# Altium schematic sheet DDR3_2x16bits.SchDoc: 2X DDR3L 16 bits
size A4; Date: 30-MAR-2016; Author: F.L; CompanyName: STMicroelectronics; Organization: MCD/TOOLS/LMS; Address1: 12, Rue Jules HOROWITZ; Address2: 38019 Grenoble; Address3: FRANCE; DocumentNumber: MB1263; Revision: C-04; SheetNumber: 8; SheetTotal: 11; Project: STM32MP157-EVAL; PageSetup: Record=PageOptions¦CenterHorizontal=True¦CenterVertical=True¦PrintScale=1.39¦XCorrection=1.00¦YCorrection=1.00¦PrintKind=1¦BorderSize=5000000¦LeftOffset=0¦BottomOffset=0¦Orientation=2¦PaperLength=1000¦PaperWidth=1000¦Scale=100¦PaperSource=15¦PrintQuality=600¦MediaType=1¦DitherType=10¦PrintScaleMode=1¦PaperKind=A3¦PaperIndex=8
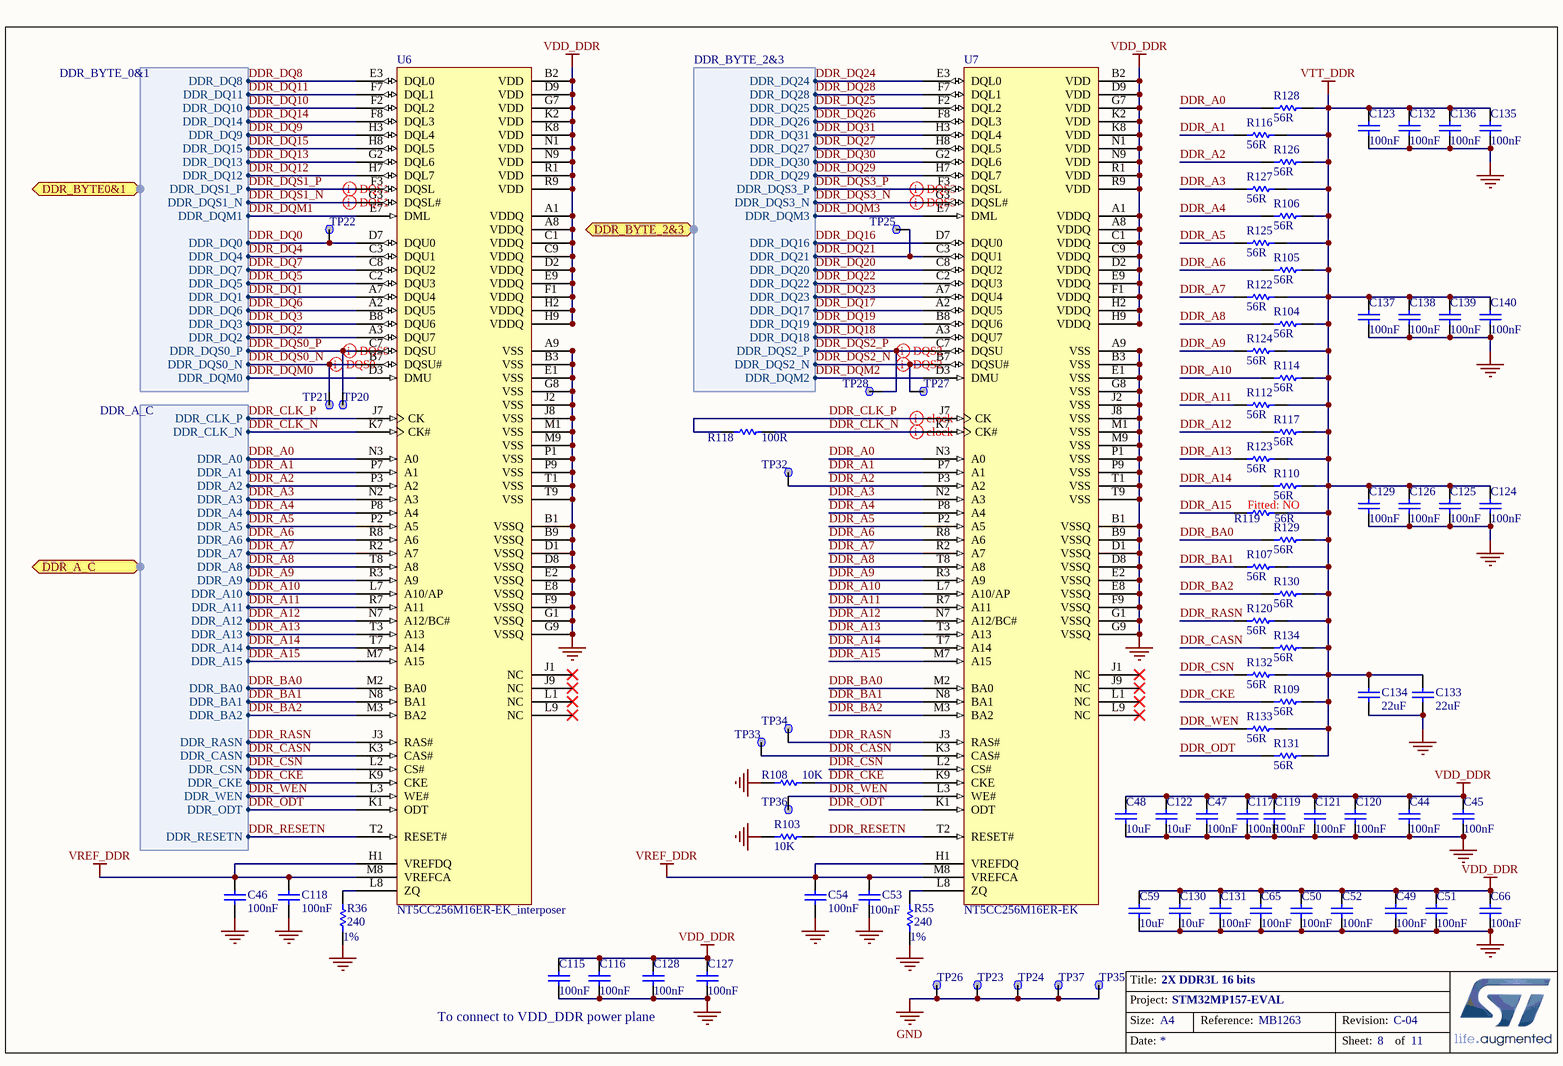
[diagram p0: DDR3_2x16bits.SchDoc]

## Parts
C44  100nF  [C0402]
C45  100nF  [C0402]
C46  100nF  [C0402]
C47  100nF  [C0402]
C48  10uF  [C0603]
C49  100nF  [C0402]
C50  100nF  [C0402]
C51  100nF  [C0402]
C52  100nF  [C0402]
C53  100nF  [C0402]
C54  100nF  [C0402]
C59  10uF  [C0603]
C65  100nF  [C0402]
C66  100nF  [C0402]
C115  100nF  [C0402]
C116  100nF  [C0402]
C117  100nF  [C0402]
C118  100nF  [C0402]
C119  100nF  [C0402]
C120  100nF  [C0402]
C121  100nF  [C0402]
C122  10uF  [C0603]
C123  100nF  [C0402]
C124  100nF  [C0402]
C125  100nF  [C0402]
C126  100nF  [C0402]
C127  100nF  [C0402]
C128  100nF  [C0402]
C129  100nF  [C0402]
C130  10uF  [C0603]
C131  100nF  [C0402]
C132  100nF  [C0402]
C133  22uF  [C0603]
C134  22uF  [C0603]
C135  100nF  [C0402]
C136  100nF  [C0402]
C137  100nF  [C0402]
C138  100nF  [C0402]
C139  100nF  [C0402]
C140  100nF  [C0402]
R36  240  Precision: 1%  [R0402]
R55  240  Precision: 1%  [R0402]
R103  10K  [R0402]
R104  56R  [R0402]
R105  56R  [R0402]
R106  56R  [R0402]
R107  56R  [R0402]
R108  10K  [R0402]
R109  56R  [R0402]
R110  56R  [R0402]
R112  56R  [R0402]
R114  56R  [R0402]
R116  56R  [R0402]
R117  56R  [R0402]
R118  100R  [R0402]
R119  56R  Fitted: NO  [R0402]
R120  56R  [R0402]
R122  56R  [R0402]
R123  56R  [R0402]
R124  56R  [R0402]
R125  56R  [R0402]
R126  56R  [R0402]
R127  56R  [R0402]
R128  56R  [R0402]
R129  56R  [R0402]
R130  56R  [R0402]
R131  56R  [R0402]
R132  56R  [R0402]
R133  56R  [R0402]
R134  56R  [R0402]
TP20  TP 0.3  [TP_SMD_0-3MM]  (value not drawn)  (no BOM)
TP21  TP 0.3  [TP_SMD_0-3MM]  (value not drawn)  (no BOM)
TP22  TP 0.6  [TP_SMD_0-6MM]  (value not drawn)  (no BOM)
TP23  TP 0.6  [TP_SMD_0-6MM]  (value not drawn)  (no BOM)
TP24  TP 0.6  [TP_SMD_0-6MM]  (value not drawn)  (no BOM)
TP25  TP 0.6  [TP_SMD_0-6MM]  (value not drawn)  (no BOM)
TP26  TP 0.6  [TP_SMD_0-6MM]  (value not drawn)  (no BOM)
TP27  TP 0.3  [TP_SMD_0-3MM]  (value not drawn)  (no BOM)
TP28  TP 0.3  [TP_SMD_0-3MM]  (value not drawn)  (no BOM)
TP32  TP 0.6  [TP_SMD_0-6MM]  (value not drawn)  (no BOM)
TP33  TP 0.6  [TP_SMD_0-6MM]  (value not drawn)  (no BOM)
TP34  TP 0.6  [TP_SMD_0-6MM]  (value not drawn)  (no BOM)
TP35  TP 0.6  [TP_SMD_0-6MM]  (value not drawn)  (no BOM)
TP36  TP 0.6  [TP_SMD_0-6MM]  (value not drawn)  (no BOM)
TP37  TP 0.6  [TP_SMD_0-6MM]  (value not drawn)  (no BOM)
U6  NT5CC256M16ER-EK_interposer  [ICC_FBGA96_9X13_8X14_P080_DI _INTERPOSER]
U7  NT5CC256M16ER-EK  [ICC_FBGA96_9X13_8X14_P080_DI]

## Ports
DDR_A_C (harness DDR_A_C), DDR_BYTE0&1 (harness DDR_BYTE_0&1), DDR_BYTE_2&3 (harness DDR_BYTE_2&3)

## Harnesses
DDR_A_C: DDR_A4, DDR_A0, DDR_A2, DDR_A1, DDR_A6, DDR_A3, DDR_A5, DDR_A7, DDR_A8, DDR_A9, DDR_A14, DDR_A10, DDR_A12, DDR_A11, DDR_BA0, DDR_A13, DDR_A15, DDR_BA1, DDR_BA2, DDR_RASN, DDR_CASN, DDR_CSN, DDR_CKE, DDR_WEN, DDR_ODT, DDR_CLK_P, DDR_CLK_N, DDR_RESETN
DDR_BYTE_0&1: DDR_DQ9, DDR_DQ8, DDR_DQ10, DDR_DQ11, DDR_DQ13, DDR_DQ14, DDR_DQ15, DDR_DQ12, DDR_DQS1_P, DDR_DQS1_N, DDR_DQ7, DDR_DQM1, DDR_DQ0, DDR_DQ1, DDR_DQ4, DDR_DQ5, DDR_DQ6, DDR_DQ3, DDR_DQ2, DDR_DQS0_P, DDR_DQS0_N, DDR_DQM0
DDR_BYTE_2&3: DDR_DQ24, DDR_DQ28, DDR_DQ25, DDR_DQ26, DDR_DQ31, DDR_DQ27, DDR_DQ30, DDR_DQ29, DDR_DQS3_P, DDR_DQS3_N, DDR_DQM3, DDR_DQ16, DDR_DQ21, DDR_DQ20, DDR_DQ22, DDR_DQ23, DDR_DQ17, DDR_DQ19, DDR_DQ18, DDR_DQS2_P, DDR_DQS2_N, DDR_DQM2

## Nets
GND: C44.2 C45.2 C46.2 C47.2 C48.1 C49.2 C50.2 C51.2 C52.2 C53.2 C54.2 C59.1 C65.2 C66.2 C115.2 C116.2 C117.2 C118.2 C119.2 C120.2 C121.2 C122.1 C123.2 C124.2 C125.2 C126.2 C127.2 C128.2 C129.2 C130.1 C131.2 C132.2 C133.1 C134.1 C135.2 C136.2 C137.2 C138.2 C139.2 C140.2 R36.1 R55.1 R103.1 R108.1 TP23.1 TP24.1 TP26.1 TP35.1 TP37.1 U6.A9(VSS) U6.B1(VSSQ) U6.B3(VSS) U6.B9(VSSQ) U6.D1(VSSQ) U6.D8(VSSQ) U6.E1(VSS) U6.E2(VSSQ) U6.E8(VSSQ) U6.F9(VSSQ) U6.G1(VSSQ) U6.G8(VSS) U6.G9(VSSQ) U6.J2(VSS) U6.J8(VSS) U6.M1(VSS) U6.M9(VSS) U6.P1(VSS) U6.P9(VSS) U6.T1(VSS) U6.T9(VSS) U7.A9(VSS) U7.B1(VSSQ) U7.B3(VSS) U7.B9(VSSQ) U7.D1(VSSQ) U7.D8(VSSQ) U7.E1(VSS) U7.E2(VSSQ) U7.E8(VSSQ) U7.F9(VSSQ) U7.G1(VSSQ) U7.G8(VSS) U7.G9(VSSQ) U7.J2(VSS) U7.J8(VSS) U7.M1(VSS) U7.M9(VSS) U7.P1(VSS) U7.P9(VSS) U7.T1(VSS) U7.T9(VSS)
VDD_DDR: C44.1 C45.1 C47.1 C48.2 C49.1 C50.1 C51.1 C52.1 C59.2 C65.1 C66.1 C115.1 C116.1 C117.1 C119.1 C120.1 C121.1 C122.2 C127.1 C128.1 C130.2 C131.1 U6.A1(VDDQ) U6.A8(VDDQ) U6.B2(VDD) U6.C1(VDDQ) U6.C9(VDDQ) U6.D2(VDDQ) U6.D9(VDD) U6.E9(VDDQ) U6.F1(VDDQ) U6.G7(VDD) U6.H2(VDDQ) U6.H9(VDDQ) U6.K2(VDD) U6.K8(VDD) U6.N1(VDD) U6.N9(VDD) U6.R1(VDD) U6.R9(VDD) U7.A1(VDDQ) U7.A8(VDDQ) U7.B2(VDD) U7.C1(VDDQ) U7.C9(VDDQ) U7.D2(VDDQ) U7.D9(VDD) U7.E9(VDDQ) U7.F1(VDDQ) U7.G7(VDD) U7.H2(VDDQ) U7.H9(VDDQ) U7.K2(VDD) U7.K8(VDD) U7.N1(VDD) U7.N9(VDD) U7.R1(VDD) U7.R9(VDD)
VREF_DDR: C46.1 C53.1 C54.1 C118.1 U6.H1(VREFDQ) U6.M8(VREFCA) U7.H1(VREFDQ) U7.M8(VREFCA)
VTT_DDR: C123.1 C124.1 C125.1 C126.1 C129.1 C132.1 C133.2 C134.2 C135.1 C136.1 C137.1 C138.1 C139.1 C140.1 R104.2 R105.2 R106.2 R107.2 R109.2 R110.2 R112.2 R114.2 R116.2 R117.2 R119.2 R120.2 R122.2 R123.2 R124.2 R125.2 R126.2 R127.2 R128.2 R129.2 R130.2 R131.2 R132.2 R133.2 R134.2
DDR_A0: R128.1 U6.N3(A0) U7.N3(A0) ; port DDR_A_C.DDR_A0
DDR_A1: R116.1 U6.P7(A1) U7.P7(A1) ; port DDR_A_C.DDR_A1
DDR_A2: R126.1 TP32.1 U6.P3(A2) U7.P3(A2) ; port DDR_A_C.DDR_A2
DDR_A3: R127.1 U6.N2(A3) U7.N2(A3) ; port DDR_A_C.DDR_A3
DDR_A4: R106.1 U6.P8(A4) U7.P8(A4) ; port DDR_A_C.DDR_A4
DDR_A5: R125.1 U6.P2(A5) U7.P2(A5) ; port DDR_A_C.DDR_A5
DDR_A6: R105.1 U6.R8(A6) U7.R8(A6) ; port DDR_A_C.DDR_A6
DDR_A7: R122.1 U6.R2(A7) U7.R2(A7) ; port DDR_A_C.DDR_A7
DDR_A8: R104.1 U6.T8(A8) U7.T8(A8) ; port DDR_A_C.DDR_A8
DDR_A9: R124.1 U6.R3(A9) U7.R3(A9) ; port DDR_A_C.DDR_A9
DDR_A10: R114.1 U6.L7(A10/AP) U7.L7(A10/AP) ; port DDR_A_C.DDR_A10
DDR_A11: R112.1 U6.R7(A11) U7.R7(A11) ; port DDR_A_C.DDR_A11
DDR_A12: R117.1 U6.N7(A12/BC#) U7.N7(A12/BC#) ; port DDR_A_C.DDR_A12
DDR_A13: R123.1 U6.T3(A13) U7.T3(A13) ; port DDR_A_C.DDR_A13
DDR_A14: R110.1 U6.T7(A14) U7.T7(A14) ; port DDR_A_C.DDR_A14
DDR_A15: R119.1 U6.M7(A15) U7.M7(A15) ; port DDR_A_C.DDR_A15
DDR_BA0: R129.1 U6.M2(BA0) U7.M2(BA0) ; port DDR_A_C.DDR_BA0
DDR_BA1: R107.1 U6.N8(BA1) U7.N8(BA1) ; port DDR_A_C.DDR_BA1
DDR_BA2: R130.1 U6.M3(BA2) U7.M3(BA2) ; port DDR_A_C.DDR_BA2
DDR_CASN: R134.1 TP33.1 U6.K3(CAS#) U7.K3(CAS#) ; port DDR_A_C.DDR_CASN
DDR_CKE: R108.2 R109.1 U6.K9(CKE) U7.K9(CKE) ; port DDR_A_C.DDR_CKE
DDR_CLK_N: R118.2 U6.K7(CK#) U7.K7(CK#) ; port DDR_A_C.DDR_CLK_N
DDR_CLK_P: R118.1 U6.J7(CK) U7.J7(CK) ; port DDR_A_C.DDR_CLK_P
DDR_CSN: R132.1 U6.L2(CS#) U7.L2(CS#) ; port DDR_A_C.DDR_CSN
DDR_DQ0: TP22.1 U6.D7(DQU0) ; port DDR_BYTE0&1.DDR_DQ0
DDR_DQ1: U6.A7(DQU4) ; port DDR_BYTE0&1.DDR_DQ1
DDR_DQ2: U6.A3(DQU7) ; port DDR_BYTE0&1.DDR_DQ2
DDR_DQ3: U6.B8(DQU6) ; port DDR_BYTE0&1.DDR_DQ3
DDR_DQ4: U6.C3(DQU1) ; port DDR_BYTE0&1.DDR_DQ4
DDR_DQ5: U6.C2(DQU3) ; port DDR_BYTE0&1.DDR_DQ5
DDR_DQ6: U6.A2(DQU5) ; port DDR_BYTE0&1.DDR_DQ6
DDR_DQ7: U6.C8(DQU2) ; port DDR_BYTE0&1.DDR_DQ7
DDR_DQ8: U6.E3(DQL0) ; port DDR_BYTE0&1.DDR_DQ8
DDR_DQ9: U6.H3(DQL4) ; port DDR_BYTE0&1.DDR_DQ9
DDR_DQ10: U6.F2(DQL2) ; port DDR_BYTE0&1.DDR_DQ10
DDR_DQ11: U6.F7(DQL1) ; port DDR_BYTE0&1.DDR_DQ11
DDR_DQ12: U6.H7(DQL7) ; port DDR_BYTE0&1.DDR_DQ12
DDR_DQ13: U6.G2(DQL6) ; port DDR_BYTE0&1.DDR_DQ13
DDR_DQ14: U6.F8(DQL3) ; port DDR_BYTE0&1.DDR_DQ14
DDR_DQ15: U6.H8(DQL5) ; port DDR_BYTE0&1.DDR_DQ15
DDR_DQ16: U7.D7(DQU0) ; port DDR_BYTE_2&3.DDR_DQ16
DDR_DQ17: U7.A2(DQU5) ; port DDR_BYTE_2&3.DDR_DQ17
DDR_DQ18: U7.A3(DQU7) ; port DDR_BYTE_2&3.DDR_DQ18
DDR_DQ19: U7.B8(DQU6) ; port DDR_BYTE_2&3.DDR_DQ19
DDR_DQ20: U7.C8(DQU2) ; port DDR_BYTE_2&3.DDR_DQ20
DDR_DQ21: TP25.1 U7.C3(DQU1) ; port DDR_BYTE_2&3.DDR_DQ21
DDR_DQ22: U7.C2(DQU3) ; port DDR_BYTE_2&3.DDR_DQ22
DDR_DQ23: U7.A7(DQU4) ; port DDR_BYTE_2&3.DDR_DQ23
DDR_DQ24: U7.E3(DQL0) ; port DDR_BYTE_2&3.DDR_DQ24
DDR_DQ25: U7.F2(DQL2) ; port DDR_BYTE_2&3.DDR_DQ25
DDR_DQ26: U7.F8(DQL3) ; port DDR_BYTE_2&3.DDR_DQ26
DDR_DQ27: U7.H8(DQL5) ; port DDR_BYTE_2&3.DDR_DQ27
DDR_DQ28: U7.F7(DQL1) ; port DDR_BYTE_2&3.DDR_DQ28
DDR_DQ29: U7.H7(DQL7) ; port DDR_BYTE_2&3.DDR_DQ29
DDR_DQ30: U7.G2(DQL6) ; port DDR_BYTE_2&3.DDR_DQ30
DDR_DQ31: U7.H3(DQL4) ; port DDR_BYTE_2&3.DDR_DQ31
DDR_DQM0: U6.D3(DMU) ; port DDR_BYTE0&1.DDR_DQM0
DDR_DQM1: U6.E7(DML) ; port DDR_BYTE0&1.DDR_DQM1
DDR_DQM2: U7.D3(DMU) ; port DDR_BYTE_2&3.DDR_DQM2
DDR_DQM3: U7.E7(DML) ; port DDR_BYTE_2&3.DDR_DQM3
DDR_DQS0_N: TP21.1 U6.B7(DQSU#) ; port DDR_BYTE0&1.DDR_DQS0_N
DDR_DQS0_P: TP20.1 U6.C7(DQSU) ; port DDR_BYTE0&1.DDR_DQS0_P
DDR_DQS1_N: U6.G3(DQSL#) ; port DDR_BYTE0&1.DDR_DQS1_N
DDR_DQS1_P: U6.F3(DQSL) ; port DDR_BYTE0&1.DDR_DQS1_P
DDR_DQS2_N: TP27.1 U7.B7(DQSU#) ; port DDR_BYTE_2&3.DDR_DQS2_N
DDR_DQS2_P: TP28.1 U7.C7(DQSU) ; port DDR_BYTE_2&3.DDR_DQS2_P
DDR_DQS3_N: U7.G3(DQSL#) ; port DDR_BYTE_2&3.DDR_DQS3_N
DDR_DQS3_P: U7.F3(DQSL) ; port DDR_BYTE_2&3.DDR_DQS3_P
DDR_ODT: R131.1 U6.K1(ODT) U7.K1(ODT) ; port DDR_A_C.DDR_ODT
DDR_RASN: R120.1 TP34.1 U6.J3(RAS#) U7.J3(RAS#) ; port DDR_A_C.DDR_RASN
DDR_RESETN: R103.2 U6.T2(RESET#) U7.T2(RESET#) ; port DDR_A_C.DDR_RESETN
DDR_WEN: R133.1 TP36.1 U6.L3(WE#) U7.L3(WE#) ; port DDR_A_C.DDR_WEN
NetR36_2: R36.2 U6.L8(ZQ)
NetR55_2: R55.2 U7.L8(ZQ)

Not connected (* = marked no-connect by the designer): U6 J1(NC)* J9(NC)* L1(NC)* L9(NC)*; U7 J1(NC)* J9(NC)* L1(NC)* L9(NC)*

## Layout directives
differential pair: DDR_CLK_N, DDR_CLK_P, DDR_DQS0_N, DDR_DQS0_P, DDR_DQS1_N, DDR_DQS1_P, DDR_DQS2_N, DDR_DQS2_P, DDR_DQS3_N, DDR_DQS3_P

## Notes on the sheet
- To connect to VDD_DDR power plane

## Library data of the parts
C44-C47 C49-C54 C65 C66 C115-C121 C123-C129 C131 C132 C135-C140 = Cap_100nF_X7R_10%_0402: Capacitor,100nF,16V,X7R,10%,0402,YAGEO; Manuf_Part_1: CC0402KRX7R7BB104; Fitted: YES; Ordered_By: Subcon
C48 C59 C122 C130 = Cap_10uF_X5R_10%_0603: Capacitor,10uF,6.3V,X5R,10%,0603,YAGEO; Manuf_Part_1: CC0603KRX5R5BB106; Ordered_By: Subcon; Fitted: YES
C133 C134 = Cap_22uF_X5R_20%_0603_MURATA: Capacitor MLCC 22µF 20% 6,3V 7,5µF@3,3V ESR=4mohm@100kHz  Z=5mohm@2MHz X5R 0603; Manuf_Part_1: GRM188R60J226MEA0J; Manuf_1: MURATA; Fitted: YES; Ordered_By: Subcon
R36 R55 = Res_240_1%_0402: Resistor,240R,0402,1%,YAGEO; Manuf_Part_1: RC0402FR-07240RL; Fitted: YES; Ordered_By: Subcon
R103 R108 = Res_10K_1%_0402: Resistor,10K,0402,1%,YAGEO; Manuf_Part_1: RC0402FR-0710KL; Order_Code: 9239359RL; Fitted: YES; Ordered_By: Subcon
R104-R107 R109 R110 R112 R114 R116 R117 R120 R122-R134 = Res_56_1%_0402: Resistor,56R,0402,1%,YAGEO; Manuf_Part_1: RC0402FR-0756RL; Order_Code: 9239081RL; Fitted: YES; Ordered_By: Subcon
R118 = Res_100_1%_0402: Resistor,100R,0402,1%,YAGEO; Manuf_Part_1: RC0402FR-07100RL; Order_Code: 9239111; Fitted: YES; Ordered_By: Subcon
R119 = Res_56_1%_0402: Resistor,56R,0402,1%,YAGEO; Manuf_Part_1: RC0402FR-0756RL; Order_Code: 9239081RL; Ordered_By: Subcon
TP20 TP21 TP27 TP28 = TP 0.3mm: Test Point; Fitted: YES
TP22-TP26 TP32-TP37 = TP 0.6mm: Test Point; Fitted: YES
U6 = NT5CC256M16ER-EK_interposer: DDR3L, 16 bits, 4Gb, NANYA, 20nm; ECCN_US/EU: EAR99; Fitted: YES; Ordered_By: Subcon
U7 = NT5CC256M16ER-EK: DDR3L, 16 bits, 4Gb, NANYA, 20nm; ECCN_US/EU: EAR99; Fitted: YES; Ordered_By: Subcon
